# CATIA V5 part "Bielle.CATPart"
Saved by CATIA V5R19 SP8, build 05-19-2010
Part number: Bielle
Bounding box of the stored display mesh (mm): x 0 to 55, y -21 to 21, z -87.827 to 87.827
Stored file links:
  C:\Users\rcousturie\Desktop\EU_thinkMotion\iao\IAO_MMS_Groupe1\vduret\vduret\vduret\CATIA_disque\Bielle.CATPart
  C:\Users\rcousturie\Desktop\EU_thinkMotion\iao\IAO_MMS_Groupe1\vduret\vduret\vduret\CATIA_disque\vduret.CATProduct
  C:\Users\rcousturie\Desktop\EU_thinkMotion\iao\IAO_MMS_Groupe1\vduret\vduret\vduret\CATIA_disque\bati.CATPart
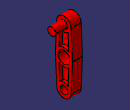
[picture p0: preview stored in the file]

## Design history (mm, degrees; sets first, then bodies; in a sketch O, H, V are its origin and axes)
External parameters (linked from other documents)
  External.diam_maneton = 20 mm
  External.diam_int_disque = 30 mm
  External.excentricite_maneton = 70 mm
  External.extrusion_disque = 25 mm
  External.extrusion_maneton = 30 mm
Body1 (main body)
  Sketch1 on yz-plane, origin (0, 0, 0), H (0, 1, 0), V (0, 0, 1)
    point P1 (0, 70)
    arc A1 centre (0, 70) radius 18 from (17.9835, 70.7714) to (-17.9835, 70.7714) ccw
    arc A2 centre (0, 0) radius 21 from (21, 0) to (20.9807, 0.9) ccw
    arc A3 centre (0, 0) radius 15 from (15, 0) to (-15, 0) ccw
    construction line L1 (-40, 0) -> (60, 0)
    point P2 (-40, 0)
    line L2 (20.9807, 0.9) -> (17.9835, 70.7714)
    point P4 (21, 0)
    line L3 (-17.9835, 70.7714) -> (-20.9807, 0.9)
    point P8 (21, 0)
    point P9 (-15, 0)
    point P10 (15, 0)
    point P11 (-21, 0)
    arc A4 centre (0, 0) radius 21 from (-20.9807, 0.9) to (-21, 0) ccw
    line L4 (-21, 0) -> (-15, 0)
    line L5 (15, 0) -> (21, 0)
    axis line L6 (0, -30) -> (0, 80)
    point P13 (0, -30)
    radius A1 = 18 {= External.diam_maneton /2+8mm}
    radius A3 = 15 {= External.diam_int_disque /2}
    radius A2 = 21 {= External.diam_int_disque /2+6mm}
    distance P1 L1 = 70 {= External.excentricite_maneton}
    coincidence: P2 H, L1 P9, L1 P10, L1 P11, A2 A4, P4 A2, P4 P8, P13 V, P1 L6
    horizontal: L1 H, L4 H, L5 H
    tangency: L2 A1, L2 A2, L3 A1, L3 A2
    vertical: L6 V
  Pad1: profile Sketch1, direction (1, 0, 0), length 25 {= External.extrusion_disque}
  Sketch2 on end face of Pad1, origin (25, 0, 0), H (0, 1, 0), V (0, 0, 1)
    arc A1 centre (0, 70) radius 16 from (-10.5261, 57.9501) to (10.5261, 57.9501) ccw
    point P1 (0, 70)
    arc A2 centre (0, 0) radius 21 from (12.2812, 17.0344) to (-12.2812, 17.0344) ccw
    line L1 (10.5261, 57.9501) -> (12.2812, 17.0344)
    reference projected line E1 (20.9291, 2.1023) -> (18.797, 51.8059) from edge [face of Pad1 from Sketch1.L2 | end face of Pad1]
    reference projected line E2 (20.9291, 2.1023) -> (18.797, 51.8059) from edge [face of Pad1 from Sketch1.L2 | end face of Pad1]
    line L2 (-10.5261, 57.9501) -> (-12.2812, 17.0344)
    reference projected line E3 (-18.797, 51.8059) -> (-20.9291, 2.1023) from edge [face of Pad1 from Sketch1.L3 | end face of Pad1]
    reference projected line E4 (-18.797, 51.8059) -> (-20.9291, 2.1023) from edge [face of Pad1 from Sketch1.L3 | end face of Pad1]
    radius A1 = 16 {= External.diam_maneton /2+6mm}
    radius A2 = 21 {= External.diam_int_disque /2+6mm}
    distance L1 E2 = 8
    distance E4 L2 = 8
    distance P1 H = 70 {= External.excentricite_maneton}
    parallelism: L1 E1, L2 E3
    coincidence: P1 V
  Pocket1: profile Sketch2, direction (-1, 0, 0), length 8
  Sketch3 on start face of Pad1, origin (0, 0, 0), H (0, -1, 0), V (0, 0, 1)
    projected line E1 (10.5261, 57.9501) -> (12.2812, 17.0344) from edge [end face of Pad1 | face of Pocket1 from Sketch2.L2]
    projected arc E2 centre (0, 70) radius 16 from (-10.5261, 57.9501) to (10.5261, 57.9501) ccw from edge [end face of Pad1 | face of Pocket1 from Sketch2.A1]
    projected line E3 (-12.2812, 17.0344) -> (-10.5261, 57.9501) from edge [end face of Pad1 | face of Pocket1 from Sketch2.L1]
    projected arc E4 centre (0, 0) radius 21 from (12.2812, 17.0344) to (-12.2812, 17.0344) ccw from edge [end face of Pad1 | face of Pocket1 from Sketch2.A2]
  Pocket2: profile Sketch3, direction (1, 0, 0), length 8
  Mirror1: of Pad1, Pocket1, Pocket2, about xy-plane
  Sketch4 on face of Mirror1, origin (25, 0, 0), H (0, 1, 0), V (0, 0, 1)
    circle A1 centre (0, 70) radius 10
    point P1 (0, 70)
    radius A1 = 10 {= External.diam_maneton /2}
    distance P1 H = 70 {= External.excentricite_maneton}
    coincidence: P1 V
  Pad2: profile Sketch4, direction (1, 0, 0), length 30 {= External.extrusion_maneton}
  Sketch5 on face of Mirror1, origin (25, 0, 0), H (0, 1, 0), V (0, 0, 1)
    circle A1 centre (0, -70) radius 10
    point P1 (0, -70)
    reference projected arc E1 centre (0, -70) radius 18 from (-17.9098, -71.8) to (17.9098, -71.8) ccw from edge [face of Mirror1 | face of Mirror1]
    radius A1 = 10 {= External.diam_maneton /2}
    coincidence: P1 V
    concentricity: A1 E1
  Pocket3: profile Sketch5, direction (-1, 0, 0), through (limit type 6)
